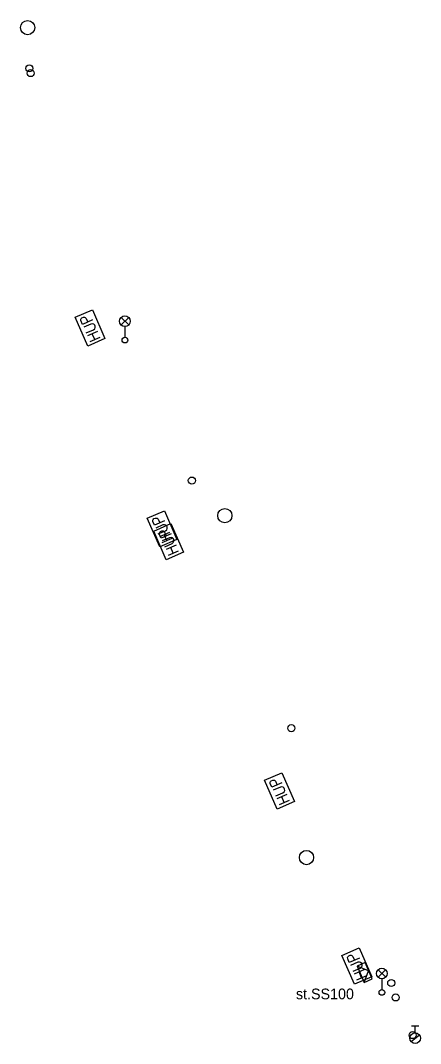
# Model space of a CAD drawing. Extents: x -762500 to -761250, y -1152983 to -1152297.
# Drawn here: x -761477.2 to -761449.1, y -1152758.9 to -1152687.1 of the extents above; entities that cross this region are included whole.
import ezdxf

# ---------------------------------------------------------------- set-up
doc = ezdxf.new("R2010")
doc.units = 0
for name, color, linetype in [('Vrstva 1', 7, 'Continuous'), ('Vrstva 2', 7, 'Continuous'), ('Vrstva 9', 7, 'Continuous')]:
    doc.layers.add(name, color=color, linetype=linetype)

msp = doc.modelspace()

# ---------------------------------------------------------------- linework, layer by layer
at = {"layer": 'Vrstva 1'}
msp.add_lwpolyline([(-761452.5, -1152754.353), (-761453, -1152753.207), (-761453.55, -1152753.447), (-761453.05, -1152754.593)], close=True, dxfattribs=at)
msp.add_lwpolyline([(-761453.05, -1152754.593), (-761452.75, -1152753.78), (-761453.55, -1152753.447)], dxfattribs=at)
at = {"layer": 'Vrstva 9'}
for p, q in [((-761470.114, -1152708.488), (-761469.586, -1152707.96)), ((-761469.578, -1152708.485), (-761470.106, -1152707.956)), ((-761469.85, -1152708.6), (-761469.85, -1152709.35)), ((-761452.084, -1152754.238), (-761451.556, -1152753.71)), ((-761451.548, -1152754.235), (-761452.076, -1152753.706)), ((-761451.82, -1152754.35), (-761451.82, -1152755.1)), ((-761449.73, -1152757.635), (-761449.23, -1152757.635)), ((-761449.48, -1152758.135), (-761449.48, -1152757.635)), ((-761449.774, -1152758.741), (-761449.184, -1152758.278))]:
    msp.add_line(p, q, dxfattribs=at)
for points in [[(-761472.461, -1152709.966), (-761473.34, -1152707.949), (-761472.129, -1152707.422), (-761471.251, -1152709.438), (-761472.461, -1152709.966)], [(-761472.824, -1152708.444), (-761472.938, -1152708.182), (-761472.941, -1152708.083), (-761472.921, -1152708.038), (-761472.867, -1152707.981), (-761472.767, -1152707.937), (-761472.687, -1152707.936), (-761472.642, -1152707.953), (-761472.571, -1152708.022), (-761472.457, -1152708.284)], [(-761472.118, -1152708.137), (-761472.824, -1152708.444)], [(-761472.56, -1152709.049), (-761472.054, -1152708.829), (-761471.967, -1152708.757), (-761471.928, -1152708.666), (-761471.931, -1152708.566), (-761471.956, -1152708.508), (-761472.027, -1152708.437), (-761472.119, -1152708.409), (-761472.231, -1152708.423), (-761472.737, -1152708.644)], [(-761471.767, -1152708.941), (-761472.473, -1152709.249)], [(-761472.296, -1152709.654), (-761471.591, -1152709.347)], [(-761471.964, -1152709.509), (-761472.14, -1152709.104)], [(-761467.411, -1152724.056), (-761468.29, -1152722.039), (-761467.079, -1152721.512), (-761466.201, -1152723.528), (-761467.411, -1152724.056)], [(-761467.774, -1152722.534), (-761467.888, -1152722.272), (-761467.891, -1152722.173), (-761467.871, -1152722.128), (-761467.817, -1152722.071), (-761467.717, -1152722.027), (-761467.637, -1152722.026), (-761467.592, -1152722.043), (-761467.521, -1152722.112), (-761467.407, -1152722.374)], [(-761466.951, -1152724.956), (-761467.83, -1152722.939), (-761466.619, -1152722.412), (-761465.741, -1152724.428), (-761466.951, -1152724.956)], [(-761467.068, -1152722.227), (-761467.774, -1152722.534)], [(-761467.51, -1152723.139), (-761467.004, -1152722.919), (-761466.917, -1152722.847), (-761466.878, -1152722.756), (-761466.881, -1152722.656), (-761466.906, -1152722.598), (-761466.977, -1152722.527), (-761467.069, -1152722.499), (-761467.181, -1152722.513), (-761467.687, -1152722.734)], [(-761467.314, -1152723.434), (-761467.428, -1152723.172), (-761467.431, -1152723.073), (-761467.411, -1152723.028), (-761467.357, -1152722.971), (-761467.257, -1152722.927), (-761467.177, -1152722.926), (-761467.132, -1152722.943), (-761467.061, -1152723.012), (-761466.947, -1152723.274)], [(-761466.717, -1152723.031), (-761467.423, -1152723.339)], [(-761466.608, -1152723.127), (-761467.314, -1152723.434)], [(-761466.914, -1152723.599), (-761467.09, -1152723.194)], [(-761467.246, -1152723.744), (-761466.541, -1152723.437)], [(-761467.05, -1152724.039), (-761466.544, -1152723.819), (-761466.457, -1152723.747), (-761466.418, -1152723.656), (-761466.421, -1152723.556), (-761466.446, -1152723.498), (-761466.517, -1152723.427), (-761466.609, -1152723.399), (-761466.721, -1152723.413), (-761467.227, -1152723.634)], [(-761466.257, -1152723.931), (-761466.963, -1152724.239)], [(-761466.786, -1152724.644), (-761466.081, -1152724.337)], [(-761466.454, -1152724.499), (-761466.63, -1152724.094)], [(-761459.171, -1152742.436), (-761460.05, -1152740.419), (-761458.839, -1152739.892), (-761457.961, -1152741.908), (-761459.171, -1152742.436)], [(-761459.534, -1152740.914), (-761459.648, -1152740.652), (-761459.651, -1152740.553), (-761459.631, -1152740.508), (-761459.577, -1152740.451), (-761459.477, -1152740.407), (-761459.397, -1152740.406), (-761459.352, -1152740.423), (-761459.281, -1152740.492), (-761459.167, -1152740.754)], [(-761458.828, -1152740.607), (-761459.534, -1152740.914)], [(-761459.27, -1152741.519), (-761458.764, -1152741.299), (-761458.677, -1152741.227), (-761458.638, -1152741.136), (-761458.641, -1152741.036), (-761458.666, -1152740.978), (-761458.737, -1152740.907), (-761458.829, -1152740.879), (-761458.941, -1152740.893), (-761459.447, -1152741.114)], [(-761458.477, -1152741.411), (-761459.183, -1152741.719)], [(-761459.006, -1152742.124), (-761458.301, -1152741.817)], [(-761458.674, -1152741.979), (-761458.85, -1152741.574)], [(-761453.741, -1152754.726), (-761454.62, -1152752.709), (-761453.409, -1152752.182), (-761452.531, -1152754.198), (-761453.741, -1152754.726)], [(-761454.104, -1152753.204), (-761454.218, -1152752.942), (-761454.221, -1152752.843), (-761454.201, -1152752.798), (-761454.147, -1152752.741), (-761454.047, -1152752.697), (-761453.967, -1152752.696), (-761453.922, -1152752.713), (-761453.851, -1152752.782), (-761453.737, -1152753.044)], [(-761453.398, -1152752.897), (-761454.104, -1152753.204)], [(-761453.84, -1152753.809), (-761453.334, -1152753.589), (-761453.247, -1152753.517), (-761453.208, -1152753.426), (-761453.211, -1152753.326), (-761453.236, -1152753.268), (-761453.307, -1152753.197), (-761453.399, -1152753.169), (-761453.511, -1152753.183), (-761454.017, -1152753.404)], [(-761453.047, -1152753.701), (-761453.753, -1152754.009)], [(-761453.576, -1152754.414), (-761452.871, -1152754.107)], [(-761453.244, -1152754.269), (-761453.42, -1152753.864)]]:
    msp.add_lwpolyline(points, dxfattribs=at)
for centre, radius in [((-761476.68, -1152687.63), 0.5), ((-761476.56, -1152690.49), 0.25), ((-761476.46, -1152690.82), 0.25), ((-761469.85, -1152708.225), 0.375), ((-761469.85, -1152709.55), 0.2), ((-761465.15, -1152719.4), 0.25), ((-761462.84, -1152721.86), 0.5), ((-761458.17, -1152736.77), 0.25), ((-761457.11, -1152745.84), 0.5), ((-761451.82, -1152753.975), 0.375), ((-761451.16, -1152754.64), 0.25), ((-761451.82, -1152755.3), 0.2), ((-761450.85, -1152755.65), 0.25), ((-761449.66, -1152758.29), 0.25), ((-761449.48, -1152758.51), 0.375)]:
    msp.add_circle(centre, radius, dxfattribs=at)

# ---------------------------------------------------------------- texts
at = {"layer": 'Vrstva 2'}
msp.add_text('st.SS100', height=0.75, dxfattribs=at).set_placement((-761457.85, -1152755.78))

doc.saveas('drawing.dxf')
